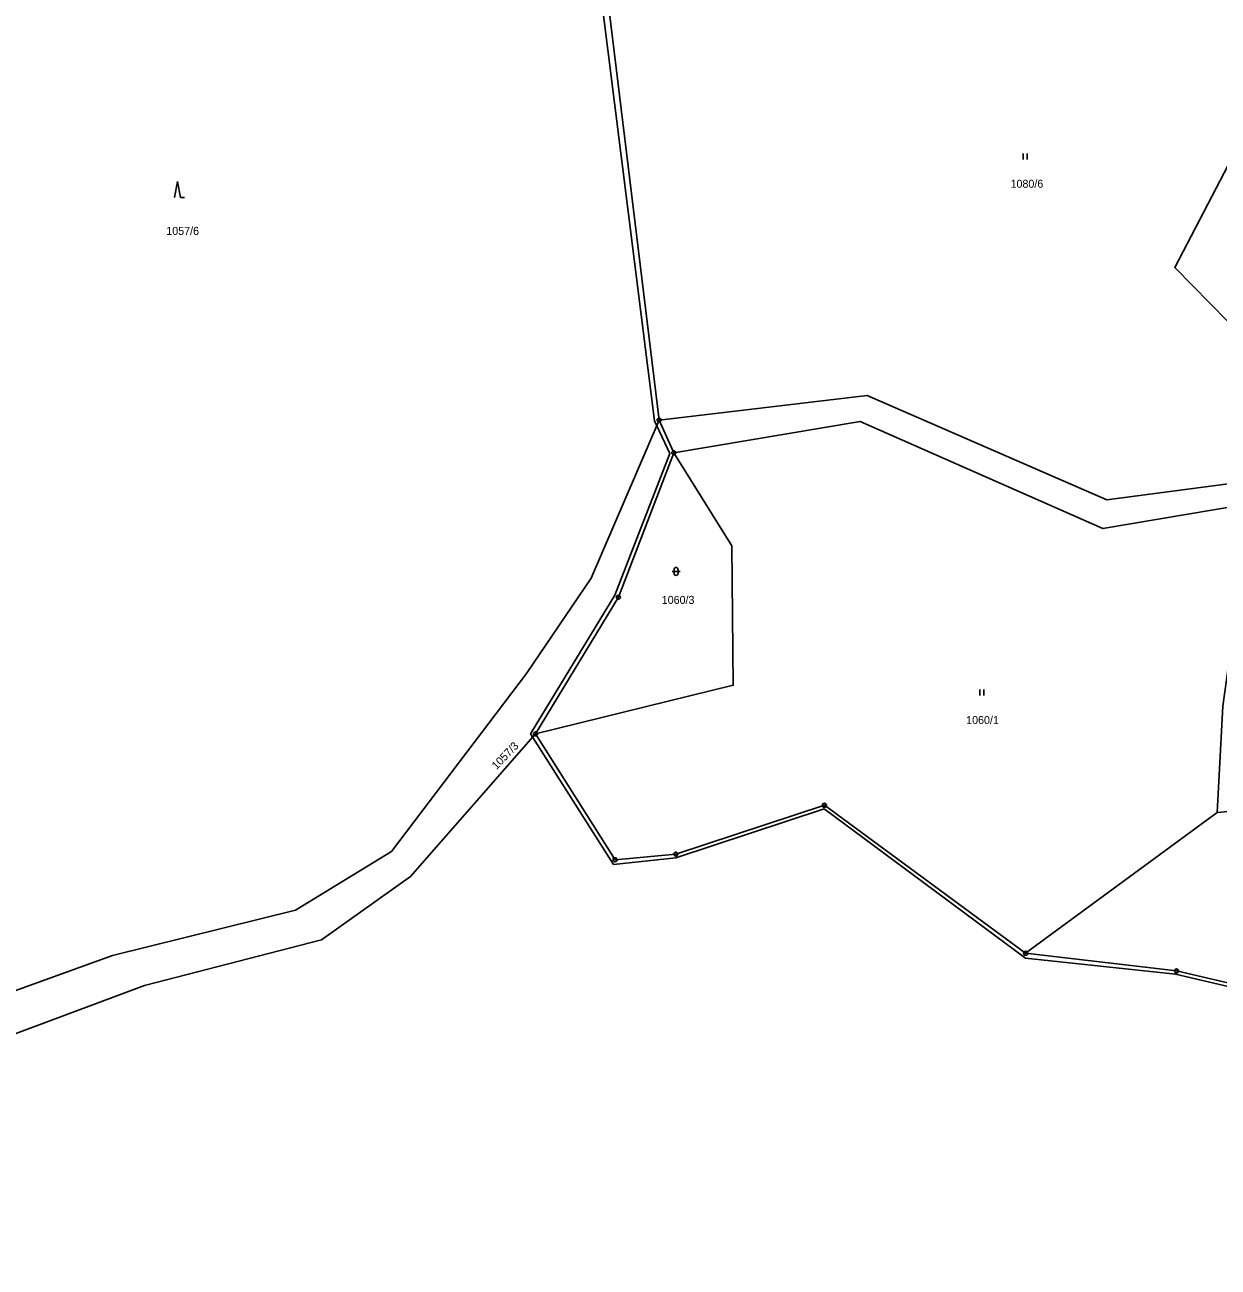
# Model space of a CAD drawing. Extents: x -745926 to -742978, y -968282 to -965689.
# Drawn here: x -745005.4 to -744856.3, y -967404.9 to -967249.8 of the extents above; entities that cross this region are included whole.
import ezdxf

# ---------------------------------------------------------------- set-up
doc = ezdxf.new("R2010")
doc.units = 0
for name, color, linetype in [('Hranice parcel', 7, 'Continuous'), ('Parcelní čísla', 7, 'Continuous'), ('Vnitřní kresba', 7, 'Continuous'), ('Značky bodu BP', 7, 'Continuous'), ('Značky kultur', 7, 'Continuous')]:
    doc.layers.add(name, color=color, linetype=linetype)

msp = doc.modelspace()

# ---------------------------------------------------------------- linework, layer by layer
at = {"layer": 'Hranice parcel'}
for p in [(-744936.45, -967214.79), (-744924.33, -967303.22)]:
    msp.add_line(p, (-744926.16, -967299.13), dxfattribs=at)
for points in [[(-744852.96, -967263.28), (-744861.74, -967280.07), (-744841.86, -967300.32)], [(-744926.16, -967299.13), (-744900.15, -967296.05), (-744870.21, -967309.08), (-744850.93, -967306.57), (-744841.86, -967300.32)], [(-744926.16, -967299.13), (-744934.65, -967318.87), (-744942.73, -967330.77), (-744959.62, -967353.03), (-744971.61, -967360.36), (-744994.47, -967365.99), (-745019.5, -967375.06), (-745048.21, -967393.63), (-745071.43, -967400.4)], [(-744843.19, -967304.69), (-744849.97, -967309.19), (-744870.7, -967312.68), (-744901.03, -967299.3), (-744924.33, -967303.22)], [(-744941.62, -967338.34), (-744931.26, -967321.26), (-744924.33, -967303.22)], [(-744924.33, -967303.22), (-744917.09, -967314.83), (-744916.9, -967332.26), (-744941.62, -967338.34)], [(-744845.12, -967310.19), (-744850.17, -967315.05), (-744836.22, -967331.25), (-744846.58, -967347.28), (-744856.42, -967348.13), (-744855.74, -967334.86), (-744852.88, -967314.56), (-744846.95, -967308.52)], [(-745077.64, -967400.97), (-745074.37, -967404.94), (-745044.78, -967397.79), (-745017.98, -967380.02), (-744990.48, -967369.76), (-744968.34, -967364.05), (-744957.22, -967356.15), (-744941.62, -967338.34)], [(-744941.62, -967338.34), (-744931.67, -967354.04), (-744924.07, -967353.35), (-744905.51, -967347.25), (-744880.37, -967365.73), (-744861.51, -967367.94), (-744834.82, -967374.19), (-744814.27, -967371.94), (-744785.51, -967369.47)]]:
    msp.add_lwpolyline(points, dxfattribs=at)
at = {"layer": 'Vnitřní kresba'}
for p, q in [((-744926.75, -967299.21), (-744937.88, -967210.62)), ((-744924.82, -967303.31), (-744926.75, -967299.21)), ((-744931.71, -967321.02), (-744924.82, -967303.31)), ((-744931.71, -967321.02), (-744942.22, -967338.32)), ((-744942.22, -967338.32), (-744931.87, -967354.64)), ((-744924.08, -967353.81), (-744905.52, -967347.7)), ((-744905.52, -967347.7), (-744880.38, -967366.35)), ((-744880.37, -967365.73), (-744856.42, -967348.13)), ((-744931.87, -967354.64), (-744924.08, -967353.81)), ((-744880.38, -967366.35), (-744861.62, -967368.36)), ((-744861.62, -967368.36), (-744834.88, -967374.61))]:
    msp.add_line(p, q, dxfattribs=at)
at = {"layer": 'Značky bodu BP'}
for centre, radius in [((-744926.16, -967299.13), 0.25), ((-744926.16, -967299.13), 0.0152), ((-744924.33, -967303.22), 0.25), ((-744924.33, -967303.22), 0.0152), ((-744931.26, -967321.26), 0.25), ((-744931.26, -967321.26), 0.0152), ((-744941.62, -967338.34), 0.25), ((-744941.62, -967338.34), 0.0152), ((-744905.51, -967347.25), 0.25), ((-744905.51, -967347.25), 0.0152), ((-744924.07, -967353.35), 0.25), ((-744931.67, -967354.04), 0.25), ((-744931.67, -967354.04), 0.0152), ((-744924.07, -967353.35), 0.0152), ((-744880.37, -967365.73), 0.25), ((-744880.37, -967365.73), 0.0152), ((-744861.51, -967367.94), 0.25), ((-744861.51, -967367.94), 0.0152)]:
    msp.add_circle(centre, radius, dxfattribs=at)
at = {"layer": 'Značky kultur'}
for p, q in [((-744880.69, -967266.56), (-744880.69, -967265.81)), ((-744880.19, -967266.56), (-744880.19, -967265.81)), ((-744986.34, -967269.31), (-744986.71, -967271.31)), ((-744985.96, -967271.31), (-744986.34, -967269.31)), ((-744985.96, -967271.31), (-744985.47, -967271.31)), ((-744924.55, -967318.04), (-744923.55, -967318.04)), ((-744924.3, -967317.79), (-744924.3, -967318.29)), ((-744923.8, -967318.29), (-744923.8, -967317.79)), ((-744886.09, -967333.55), (-744886.09, -967332.8)), ((-744885.58, -967333.55), (-744885.58, -967332.8))]:
    msp.add_line(p, q, dxfattribs=at)
for centre, start, end in [((-744924.05, -967317.79), 0, 180), ((-744924.05, -967318.29), 180, 359.9879)]:
    msp.add_arc(centre, 0.25, start, end, dxfattribs=at)

# ---------------------------------------------------------------- texts
at = {"layer": 'Parcelní čísla'}
for s, p in [('1080/6', (-744882.25, -967270.11)), ('1057/6', (-744987.75, -967276)), ('1060/3', (-744925.84, -967322.09)), ('1060/1', (-744887.8, -967337.1))]:
    msp.add_text(s, height=1, dxfattribs=at).set_placement(p)
msp.add_text('1057/3', height=1, rotation=46, dxfattribs=at).set_placement((-744946.48, -967342.86))

doc.saveas('drawing.dxf')
